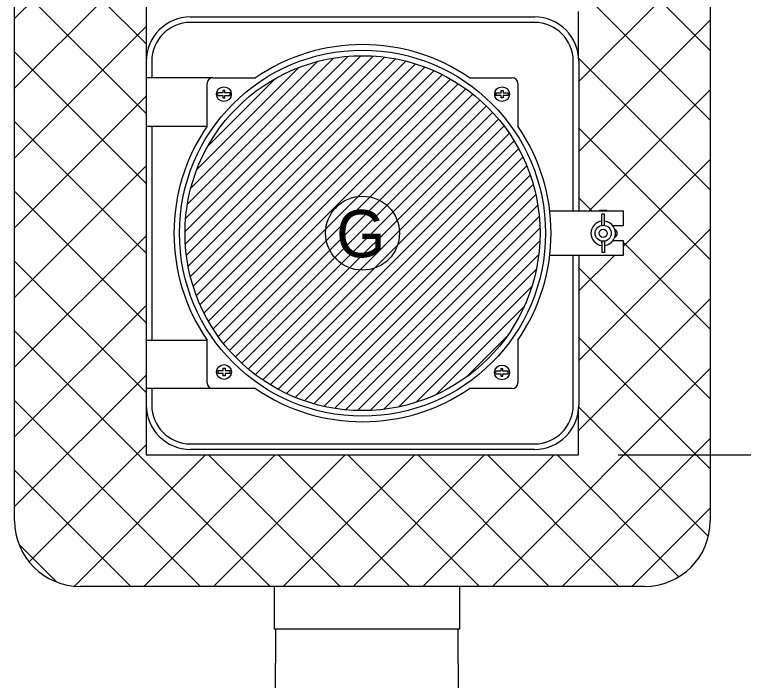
# Model space of a CAD drawing. Extents: x 99862 to 103680, y 99470 to 105076.
# Drawn here: x 101307.4 to 101529.2, y 104560.5 to 104763.1 of the extents above; entities that cross this region are included whole.
import ezdxf

# ---------------------------------------------------------------- set-up
doc = ezdxf.new("R2010")
doc.units = 0
for name, color, linetype in [('Level 1', 7, 'Continuous'), ('Level 12', 7, 'Continuous'), ('Level 15', 7, 'Continuous'), ('Level 18', 7, 'Continuous'), ('Level 20', 7, 'Continuous'), ('Level 4', 7, 'Continuous'), ('Level 7', 7, 'Continuous'), ('Level 8', 7, 'Continuous')]:
    doc.layers.add(name, color=color, linetype=linetype)

msp = doc.modelspace()

# ---------------------------------------------------------------- linework, layer by layer
at = {"layer": 'Level 1'}
for p, q in [((101307.44, 104609.1), (101307.44, 105054.1)), ((101519.12, 105054.1), (101519.12, 104609.1)), ((101347.44, 105034.1), (101347.44, 104629.1)), ((101307.44, 104761.9), (101347.44, 104801.9)), ((101347.44, 104754.18), (101307.44, 104794.18)), ((101519.12, 104752.21), (101479.07, 104792.26)), ((101307.44, 104740.69), (101347.44, 104780.69)), ((101479.07, 104742.61), (101519.12, 104782.65)), ((101347.44, 104732.97), (101307.44, 104772.97)), ((101519.12, 104731), (101479.07, 104771.05)), ((101479.07, 104750.06), (101479.07, 104764.1)), ((101360.99, 104762.41), (101465.62, 104762.41)), ((101465.62, 104760.73), (101360.99, 104760.73)), ((101479.07, 104721.39), (101519.12, 104761.44)), ((101307.44, 104719.47), (101347.44, 104759.47)), ((101347.44, 104711.75), (101307.44, 104751.75)), ((101519.12, 104709.79), (101479.07, 104749.84)), ((101349.18, 104748.91), (101349.18, 104743.85)), ((101477.43, 104703.35), (101477.43, 104748.91)), ((101479.12, 104748.91), (101479.12, 104703.35)), ((101367.74, 104743.85), (101347.44, 104743.85)), ((101367.74, 104743.85), (101380.76, 104743.85)), ((101445.85, 104743.85), (101458.87, 104743.85)), ((101366.06, 104729.15), (101366.06, 104742.16)), ((101460.56, 104742.16), (101460.56, 104729.15)), ((101482.24, 104703.35), (101519.12, 104740.23)), ((101307.44, 104698.26), (101347.44, 104738.26)), ((101347.44, 104690.54), (101307.44, 104730.54)), ((101347.44, 104729.15), (101366.06, 104729.15)), ((101349.18, 104729.15), (101349.18, 104664.05)), ((101519.12, 104688.57), (101479.07, 104728.62)), ((101492.62, 104692.51), (101519.12, 104719.01)), ((101307.44, 104677.05), (101347.44, 104717.05)), ((101347.44, 104669.33), (101307.44, 104709.33)), ((101483.13, 104703.35), (101479.07, 104707.41)), ((101470.28, 104703.35), (101478.24, 104703.35)), ((101478.31, 104703.35), (101492.62, 104703.35)), ((101492.6, 104703.35), (101492.6, 104703.4)), ((101492.62, 104703.35), (101492.62, 104698.85)), ((101492.62, 104698.85), (101489.48, 104698.85)), ((101479.07, 104657.75), (101519.12, 104697.8)), ((101307.44, 104655.83), (101347.44, 104695.83)), ((101489.57, 104694.4), (101492.62, 104694.4)), ((101492.62, 104694.4), (101492.62, 104689.85)), ((101519.12, 104667.36), (101492.62, 104693.86)), ((101478.24, 104689.85), (101470.28, 104689.85)), ((101477.43, 104644.29), (101477.43, 104689.85)), ((101492.62, 104689.85), (101478.31, 104689.85)), ((101479.07, 104678.97), (101489.96, 104689.85)), ((101479.12, 104689.85), (101479.12, 104644.29)), ((101347.44, 104648.11), (101307.44, 104688.11)), ((101519.12, 104646.15), (101479.07, 104686.2)), ((101479.07, 104636.54), (101519.12, 104676.59)), ((101307.44, 104634.62), (101347.44, 104674.62)), ((101385.25, 104589.1), (101307.44, 104666.9)), ((101347.44, 104664.05), (101366.06, 104664.05)), ((101366.06, 104651.04), (101366.06, 104664.05)), ((101460.56, 104664.05), (101460.56, 104651.04)), ((101519.12, 104624.93), (101479.07, 104664.98)), ((101452.85, 104589.1), (101519.12, 104655.38)), ((101307.44, 104613.41), (101347.44, 104653.41)), ((101367.74, 104649.35), (101347.44, 104649.35)), ((101349.18, 104649.35), (101349.18, 104644.29)), ((101380.76, 104649.35), (101367.74, 104649.35)), ((101458.87, 104649.35), (101445.85, 104649.35)), ((101364.03, 104589.1), (101307.44, 104645.69)), ((101518.54, 104604.3), (101479.07, 104643.77)), ((101479.07, 104629.1), (101479.07, 104643.14)), ((101474.06, 104589.1), (101519.12, 104634.16)), ((101311.84, 104596.59), (101347.44, 104632.19)), ((101360.99, 104632.48), (101465.62, 104632.48)), ((101465.62, 104630.79), (101360.99, 104630.79)), ((101325.65, 104589.18), (101365.57, 104629.1)), ((101346.78, 104589.1), (101386.78, 104629.1)), ((101347.44, 104629.1), (101479.07, 104629.1)), ((101406.46, 104589.1), (101366.46, 104629.1)), ((101367.99, 104589.1), (101407.99, 104629.1)), ((101427.67, 104589.1), (101387.67, 104629.1)), ((101389.21, 104589.1), (101429.21, 104629.1)), ((101448.88, 104589.1), (101408.88, 104629.1)), ((101410.42, 104589.1), (101450.42, 104629.1)), ((101470.1, 104589.1), (101430.1, 104629.1)), ((101431.63, 104589.1), (101471.63, 104629.1)), ((101491.31, 104589.1), (101451.31, 104629.1)), ((101509.57, 104592.05), (101472.52, 104629.1)), ((101342.82, 104589.1), (101307.44, 104624.48)), ((101495.27, 104589.1), (101519.12, 104612.95)), ((101320.28, 104590.43), (101308.77, 104601.93)), ((101499.12, 104589.1), (101327.44, 104589.1))]:
    msp.add_line(p, q, dxfattribs=at)
for radius in [55.69, 54]:
    msp.add_circle((101413.31, 104696.6), radius, dxfattribs=at)
for centre, radius, start, end in [((101360.99, 104748.91), 13.5, 90, 180), ((101360.99, 104748.91), 11.81, 90, 180), ((101465.62, 104748.91), 13.5, 0, 90), ((101465.62, 104748.91), 11.81, 0, 90), ((101413.31, 104696.6), 57.38, 55.4397, 124.5603), ((101367.74, 104742.16), 1.69, 90, 180), ((101458.87, 104742.16), 1.69, 0, 90), ((101413.31, 104696.6), 57.38, 145.4397, 214.5603), ((101413.31, 104696.6), 57.38, 325.4397, 34.5603), ((101367.74, 104651.04), 1.69, 180, 270), ((101458.87, 104651.04), 1.69, 270, 0), ((101413.31, 104696.6), 57.38, 235.4397, 304.5603), ((101360.99, 104644.29), 13.5, 180, 270), ((101360.99, 104644.29), 11.81, 180, 270), ((101465.62, 104644.29), 13.5, 270, 0), ((101465.62, 104644.29), 11.81, 270, 0), ((101327.44, 104609.1), 20, 180, 270), ((101499.12, 104609.1), 20, 270, 0)]:
    msp.add_arc(centre, radius, start, end, dxfattribs=at)
at = {"layer": 'Level 12'}
for p, q in [((101359.33, 104697.11), (101412.81, 104750.59)), ((101359.42, 104693.38), (101416.52, 104750.48)), ((101359.52, 104701.12), (101408.79, 104750.39)), ((101359.74, 104689.88), (101420.02, 104750.16)), ((101360.06, 104705.47), (101404.43, 104749.84)), ((101360.26, 104686.58), (101423.32, 104749.64)), ((101360.95, 104683.46), (101426.45, 104748.96)), ((101361.1, 104710.33), (101399.59, 104748.82)), ((101361.79, 104680.48), (101429.44, 104748.12)), ((101362.77, 104677.64), (101432.29, 104747.15)), ((101362.9, 104715.95), (101393.94, 104746.99)), ((101363.88, 104674.92), (101434.99, 104746.04)), ((101365.09, 104672.32), (101437.58, 104744.81)), ((101366.35, 104723.22), (101386.72, 104743.59)), ((101366.42, 104669.83), (101440.06, 104743.48)), ((101367.86, 104667.46), (101442.44, 104742.04)), ((101369.41, 104665.19), (101444.73, 104740.5)), ((101371.06, 104663.01), (101446.91, 104738.87)), ((101372.79, 104660.93), (101448.98, 104737.12)), ((101374.62, 104658.94), (101450.95, 104735.28)), ((101376.56, 104657.06), (101452.84, 104733.35)), ((101378.59, 104655.27), (101454.64, 104731.33)), ((101380.71, 104653.58), (101456.34, 104729.21)), ((101382.93, 104651.98), (101457.93, 104726.97)), ((101385.24, 104650.47), (101459.42, 104724.65)), ((101387.68, 104649.09), (101460.81, 104722.22)), ((101390.22, 104647.81), (101462.1, 104719.69)), ((101392.87, 104646.65), (101463.28, 104717.05)), ((101395.64, 104645.6), (101464.32, 104714.28)), ((101398.54, 104644.68), (101465.23, 104711.37)), ((101401.59, 104643.91), (101466, 104708.32)), ((101404.79, 104643.29), (101466.61, 104705.11)), ((101408.18, 104642.86), (101467.04, 104701.72)), ((101411.77, 104642.63), (101467.26, 104698.13)), ((101415.63, 104642.67), (101467.24, 104694.29)), ((101419.77, 104643), (101466.91, 104690.14)), ((101424.36, 104643.77), (101466.13, 104685.54)), ((101429.52, 104645.11), (101464.82, 104680.41)), ((101435.72, 104647.5), (101462.44, 104674.21)), ((101444.8, 104652.75), (101457.21, 104665.16))]:
    msp.add_line(p, q, dxfattribs=at)
at = {"layer": 'Level 15'}
msp.add_line((101491.07, 104629.1), (101800.13, 104629.1), dxfattribs=at)
at = {"layer": 'Level 18'}
msp.add_circle((101413.31, 104696.6), 11.25, dxfattribs=at)
at = {"layer": 'Level 4'}
for p, q in [((101485.42, 104703.63), (101487.64, 104703.63)), ((101485.42, 104703.63), (101485.42, 104703.4)), ((101487.64, 104703.63), (101487.64, 104703.63)), ((101487.64, 104703.4), (101487.64, 104703.63)), ((101486.91, 104702.38), (101486.15, 104702.38)), ((101486.15, 104700.54), (101486.15, 104702.38)), ((101486.91, 104700.54), (101486.91, 104702.38)), ((101486.15, 104699.73), (101486.15, 104700.54)), ((101486.15, 104699.14), (101486.15, 104699.73)), ((101486.91, 104699.73), (101486.91, 104700.54)), ((101486.91, 104699.14), (101486.91, 104699.73)), ((101486.15, 104694), (101486.15, 104693.4)), ((101486.91, 104694), (101486.91, 104693.4)), ((101486.15, 104693.4), (101486.15, 104692.59)), ((101486.15, 104692.59), (101486.15, 104690.75)), ((101486.91, 104693.4), (101486.91, 104692.59)), ((101486.91, 104692.59), (101486.91, 104690.75)), ((101486.91, 104690.75), (101486.15, 104690.75))]:
    msp.add_line(p, q, dxfattribs=at)
for centre, radius in [((101371.13, 104738.9), 2.25), ((101455.78, 104738.9), 2.25), ((101486.53, 104696.57), 2.45), ((101486.53, 104696.55), 1.25), ((101371.18, 104654.35), 2.25), ((101455.73, 104654.21), 2.25)]:
    msp.add_circle(centre, radius, dxfattribs=at)
for centre, radius, start, end in [((101371.13, 104738.9), 1.91, 167.4639, 192.4931), ((101371.13, 104738.9), 1.91, 347.5069, 12.5361), ((101455.78, 104738.9), 1.91, 167.4639, 192.4931), ((101455.78, 104738.9), 1.91, 347.5069, 12.5361), ((101486.53, 104696.57), 3.73, 95.8352, 264.1648), ((101486.53, 104696.57), 2.89, 97.5642, 97.5998), ((101486.53, 104696.57), 3.73, 32.2813, 84.1648), ((101486.53, 104696.57), 2.89, 82.4002, 82.4567), ((101486.53, 104696.57), 3.73, 275.8352, 32.2813), ((101489.54, 104696.55), 1.25, 295.8954, 63.3748), ((101486.53, 104696.57), 2.89, 262.4002, 262.4483), ((101486.53, 104696.57), 2.89, 277.5551, 277.5998), ((101371.18, 104654.35), 1.91, 167.5069, 192.5361), ((101371.18, 104654.35), 1.91, 347.4639, 12.4931), ((101455.73, 104654.21), 1.91, 167.5069, 192.5361), ((101455.73, 104654.21), 1.91, 347.4639, 12.4931)]:
    msp.add_arc(centre, radius, start, end, dxfattribs=at)
for points, degree in [([(101370.84, 104739.31), (101370.8, 104739.31), (101370.76, 104739.31), (101370.71, 104739.31), (101370.44, 104739.31), (101370.16, 104739.31), (101369.9, 104739.31), (101369.67, 104739.31), (101369.45, 104739.31), (101369.27, 104739.31)], 3), ([(101369.27, 104738.49), (101369.41, 104738.49), (101369.57, 104738.49), (101369.75, 104738.49), (101369.97, 104738.49), (101370.21, 104738.49), (101370.46, 104738.49), (101370.58, 104738.49), (101370.71, 104738.49), (101370.84, 104738.49)], 3), ([(101371.44, 104740.02), (101371.34, 104740.02), (101371.24, 104740.02), (101371.14, 104740.02), (101371.04, 104740.02), (101370.94, 104740.02), (101370.84, 104740.02)], 3), ([(101370.84, 104740.02), (101370.84, 104739.92), (101370.84, 104739.81), (101370.84, 104739.69), (101370.84, 104739.57), (101370.84, 104739.44), (101370.84, 104739.31)], 3), ([(101370.84, 104738.49), (101370.84, 104738.24), (101370.84, 104738), (101370.84, 104737.77)], 2), ([(101371.44, 104739.31), (101371.44, 104739.55), (101371.44, 104739.8), (101371.44, 104740.02)], 2), ([(101372.99, 104739.31), (101372.85, 104739.31), (101372.68, 104739.31), (101372.5, 104739.31), (101372.28, 104739.31), (101372.04, 104739.31), (101371.8, 104739.31), (101371.68, 104739.31), (101371.56, 104739.31), (101371.44, 104739.31)], 3), ([(101371.44, 104738.49), (101371.47, 104738.49), (101371.51, 104738.49), (101371.54, 104738.49), (101371.82, 104738.49), (101372.1, 104738.49), (101372.35, 104738.49), (101372.59, 104738.49), (101372.81, 104738.49), (101372.99, 104738.49)], 3), ([(101371.44, 104737.77), (101371.44, 104737.88), (101371.44, 104737.99), (101371.44, 104738.1), (101371.44, 104738.23), (101371.44, 104738.36), (101371.44, 104738.49)], 3), ([(101453.91, 104739.31), (101454.06, 104739.31), (101454.23, 104739.31), (101454.4, 104739.31), (101454.62, 104739.31), (101454.86, 104739.31), (101455.11, 104739.31), (101455.23, 104739.31), (101455.35, 104739.31), (101455.47, 104739.31)], 3), ([(101455.47, 104738.49), (101455.43, 104738.49), (101455.4, 104738.49), (101455.36, 104738.49), (101455.09, 104738.49), (101454.81, 104738.49), (101454.55, 104738.49), (101454.32, 104738.49), (101454.1, 104738.49), (101453.91, 104738.49)], 3), ([(101455.47, 104739.31), (101455.47, 104739.55), (101455.47, 104739.8), (101455.47, 104740.02)], 2), ([(101455.47, 104740.02), (101455.57, 104740.02), (101455.67, 104740.02), (101455.77, 104740.02), (101455.87, 104740.02), (101455.97, 104740.02), (101456.07, 104740.02)], 3), ([(101455.47, 104737.77), (101455.47, 104737.88), (101455.47, 104737.99), (101455.47, 104738.1), (101455.47, 104738.23), (101455.47, 104738.36), (101455.47, 104738.49)], 3), ([(101456.07, 104740.02), (101456.07, 104739.92), (101456.07, 104739.81), (101456.07, 104739.69), (101456.07, 104739.57), (101456.07, 104739.44), (101456.07, 104739.31)], 3), ([(101456.07, 104739.31), (101456.11, 104739.31), (101456.15, 104739.31), (101456.19, 104739.31), (101456.47, 104739.31), (101456.75, 104739.31), (101457, 104739.31), (101457.24, 104739.31), (101457.46, 104739.31), (101457.64, 104739.31)], 3), ([(101457.64, 104738.49), (101457.5, 104738.49), (101457.33, 104738.49), (101457.15, 104738.49), (101456.94, 104738.49), (101456.69, 104738.49), (101456.45, 104738.49), (101456.32, 104738.49), (101456.2, 104738.49), (101456.07, 104738.49)], 3), ([(101456.07, 104738.49), (101456.07, 104738.24), (101456.07, 104738), (101456.07, 104737.77)], 2), ([(101370.84, 104737.77), (101370.94, 104737.77), (101371.04, 104737.77), (101371.14, 104737.77), (101371.24, 104737.77), (101371.34, 104737.77), (101371.44, 104737.77)], 3), ([(101456.07, 104737.77), (101455.97, 104737.77), (101455.87, 104737.77), (101455.77, 104737.77), (101455.67, 104737.77), (101455.57, 104737.77), (101455.47, 104737.77)], 3), ([(101486.15, 104699.1), (101486.15, 104699.14), (101486.15, 104699.19), (101486.15, 104699.23), (101486.15, 104699.26), (101486.15, 104699.3), (101486.15, 104699.33), (101486.15, 104699.36), (101486.15, 104699.38), (101486.15, 104699.4), (101486.15, 104699.42), (101486.15, 104699.43), (101486.15, 104699.43), (101486.15, 104699.43), (101486.15, 104699.43), (101486.15, 104699.42), (101486.15, 104699.42), (101486.15, 104699.41), (101486.15, 104699.41)], 3), ([(101486.15, 104699.14), (101486.15, 104699.23), (101486.15, 104699.32), (101486.15, 104699.41)], 2), ([(101486.91, 104699.14), (101486.91, 104699.23), (101486.91, 104699.32), (101486.91, 104699.41)], 2), ([(101486.15, 104693.72), (101486.15, 104693.71), (101486.15, 104693.7), (101486.15, 104693.7), (101486.15, 104693.7), (101486.15, 104693.71), (101486.15, 104693.72), (101486.15, 104693.74), (101486.15, 104693.76), (101486.15, 104693.79), (101486.15, 104693.81), (101486.15, 104693.85), (101486.15, 104693.88), (101486.15, 104693.92), (101486.15, 104693.96), (101486.15, 104694), (101486.15, 104694.01), (101486.15, 104694.02), (101486.15, 104694.03)], 3), ([(101486.15, 104694), (101486.15, 104693.9), (101486.15, 104693.81), (101486.15, 104693.72)], 2), ([(101486.91, 104694.03), (101486.91, 104693.99), (101486.91, 104693.95), (101486.91, 104693.91), (101486.91, 104693.87), (101486.91, 104693.83), (101486.91, 104693.8), (101486.91, 104693.77), (101486.91, 104693.75), (101486.91, 104693.73), (101486.91, 104693.72), (101486.91, 104693.71), (101486.91, 104693.7), (101486.91, 104693.7), (101486.91, 104693.7), (101486.91, 104693.71), (101486.91, 104693.72), (101486.91, 104693.72), (101486.91, 104693.72)], 3), ([(101486.91, 104694), (101486.91, 104693.9), (101486.91, 104693.81), (101486.91, 104693.72)], 2), ([(101369.32, 104654.77), (101369.46, 104654.77), (101369.62, 104654.77), (101369.8, 104654.77), (101370.02, 104654.77), (101370.26, 104654.77), (101370.51, 104654.77), (101370.63, 104654.77), (101370.76, 104654.77), (101370.89, 104654.77)], 3), ([(101370.89, 104655.48), (101370.99, 104655.48), (101371.09, 104655.48), (101371.19, 104655.48), (101371.29, 104655.48), (101371.39, 104655.48), (101371.49, 104655.48)], 3), ([(101370.89, 104654.77), (101370.89, 104655.01), (101370.89, 104655.25), (101370.89, 104655.48)], 2), ([(101371.49, 104655.48), (101371.49, 104655.37), (101371.49, 104655.26), (101371.49, 104655.15), (101371.49, 104655.02), (101371.49, 104654.89), (101371.49, 104654.77)], 3), ([(101371.49, 104654.77), (101371.52, 104654.77), (101371.56, 104654.77), (101371.59, 104654.77), (101371.87, 104654.77), (101372.15, 104654.77), (101372.4, 104654.77), (101372.64, 104654.77), (101372.86, 104654.77), (101373.04, 104654.77)], 3), ([(101455.42, 104654.62), (101455.38, 104654.62), (101455.35, 104654.62), (101455.32, 104654.62), (101455.04, 104654.62), (101454.76, 104654.62), (101454.5, 104654.62), (101454.27, 104654.62), (101454.05, 104654.62), (101453.87, 104654.62)], 3), ([(101455.42, 104655.33), (101455.42, 104655.22), (101455.42, 104655.11), (101455.42, 104655), (101455.42, 104654.88), (101455.42, 104654.75), (101455.42, 104654.62)], 3), ([(101456.02, 104655.33), (101455.92, 104655.33), (101455.82, 104655.33), (101455.72, 104655.33), (101455.62, 104655.33), (101455.52, 104655.33), (101455.42, 104655.33)], 3), ([(101456.02, 104654.62), (101456.02, 104654.86), (101456.02, 104655.11), (101456.02, 104655.33)], 2), ([(101457.59, 104654.62), (101457.45, 104654.62), (101457.28, 104654.62), (101457.11, 104654.62), (101456.89, 104654.62), (101456.64, 104654.62), (101456.4, 104654.62), (101456.27, 104654.62), (101456.15, 104654.62), (101456.02, 104654.62)], 3), ([(101370.89, 104653.94), (101370.85, 104653.94), (101370.8, 104653.94), (101370.76, 104653.94), (101370.48, 104653.94), (101370.2, 104653.94), (101369.95, 104653.94), (101369.72, 104653.94), (101369.5, 104653.94), (101369.32, 104653.94)], 3), ([(101370.89, 104653.23), (101370.89, 104653.34), (101370.89, 104653.45), (101370.89, 104653.56), (101370.89, 104653.68), (101370.89, 104653.81), (101370.89, 104653.94)], 3), ([(101371.49, 104653.23), (101371.39, 104653.23), (101371.29, 104653.23), (101371.19, 104653.23), (101371.09, 104653.23), (101370.99, 104653.23), (101370.89, 104653.23)], 3), ([(101371.49, 104653.94), (101371.49, 104653.7), (101371.49, 104653.45), (101371.49, 104653.23)], 2), ([(101373.04, 104653.94), (101372.9, 104653.94), (101372.73, 104653.94), (101372.55, 104653.94), (101372.33, 104653.94), (101372.09, 104653.94), (101371.84, 104653.94), (101371.73, 104653.94), (101371.61, 104653.94), (101371.49, 104653.94)], 3), ([(101453.87, 104653.79), (101454.01, 104653.79), (101454.18, 104653.79), (101454.36, 104653.79), (101454.57, 104653.79), (101454.82, 104653.79), (101455.06, 104653.79), (101455.18, 104653.79), (101455.3, 104653.79), (101455.42, 104653.79)], 3), ([(101455.42, 104653.79), (101455.42, 104653.55), (101455.42, 104653.31), (101455.42, 104653.08)], 2), ([(101455.42, 104653.08), (101455.52, 104653.08), (101455.62, 104653.08), (101455.72, 104653.08), (101455.82, 104653.08), (101455.92, 104653.08), (101456.02, 104653.08)], 3), ([(101456.02, 104653.08), (101456.02, 104653.19), (101456.02, 104653.3), (101456.02, 104653.41), (101456.02, 104653.54), (101456.02, 104653.66), (101456.02, 104653.79)], 3), ([(101456.02, 104653.79), (101456.06, 104653.79), (101456.1, 104653.79), (101456.14, 104653.79), (101456.42, 104653.79), (101456.7, 104653.79), (101456.96, 104653.79), (101457.19, 104653.79), (101457.41, 104653.79), (101457.59, 104653.79)], 3)]:
    msp.add_open_spline(points, degree=degree, dxfattribs=at)
at = {"layer": 'Level 7'}
for p, q in [((101386.42, 104589.1), (101386.42, 104576.23)), ((101442.94, 104576.23), (101442.94, 104589.1)), ((101386.42, 104576.23), (101442.94, 104576.23))]:
    msp.add_line(p, q, dxfattribs=at)
at = {"layer": 'Level 8'}
for p, q in [((101386.62, 104507.94), (101386.97, 104576.23)), ((101442.34, 104576.23), (101443.31, 104390.38))]:
    msp.add_line(p, q, dxfattribs=at)

# ---------------------------------------------------------------- texts
at = {"layer": 'Level 20'}
msp.add_text('G', height=14.4, dxfattribs=at).set_placement((101405.3, 104689.25))

doc.saveas('drawing.dxf')
